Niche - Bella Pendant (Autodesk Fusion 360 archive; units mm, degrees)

design "Bella" references "Niche - Chief Architect - Luxe Single Pendant Cordset", "Bella", "Luxe Single Pendant Cordset - 4ft Standard"
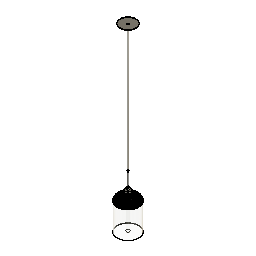
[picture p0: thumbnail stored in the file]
external_derived "ExternalDerived1" bodies "Bella"
external_derived "ExternalDerived2" bodies "Socket Body", "Shade Ring", "Shade Ring +Collar", "Socket", "Body1", "Metal Strain Relief", "Fabric Cord (1)", "Stem (Threaded)"
move "Move1"
external_derived "ExternalDerived3" bodies "T8-Bulb"
move "Move2" TranslateX 0 TranslateY 0 TranslateZ 25.4
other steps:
derived_base_feature "Derived Base Feature1" bodies "Body8", "Bella"
derived_base_feature "Derived Base Feature2" bodies "Socket Body", "Shade Ring", "Shade Ring +Collar", "Socket", "Body1", "Metal Strain Relief", "Fabric Cord (1)", "Stem (Threaded)"
derived_base_feature "Derived Base Feature3" bodies "T8-Bulb"
named bodies: "Body8", "Bella", "Socket Body", "Shade Ring", "Shade Ring +Collar", "Socket", "Body1", "Metal Strain Relief", "Fabric Cord (1)", "Stem (Threaded)", "Cap (Threaded)", "T8-Bulb"

design "Luxe Single Pendant Cordset - 4ft Standard" references "Luxe Canopy - Single Pendant Cordset"
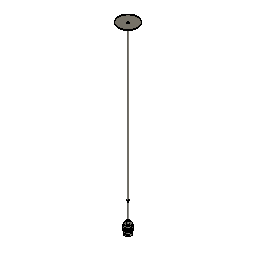
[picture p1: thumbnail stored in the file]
external_derived "ExternalDerived2" bodies "Cap (Threaded)"
move "Move1"
move "Move2"
offset_faces "OffsetFaces1" distance 1051.56
move "Move3"
move "Move4"
move "Move5"
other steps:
derived_base_feature "Derived Base Feature9" bodies "Socket Body", "Shade Ring", "Shade Ring +Collar", "Socket"
derived_base_feature "Derived Base Feature10" bodies "Body1"
derived_base_feature "Derived Base Feature12" bodies "Metal Strain Relief"
derived_base_feature "Derived Base Feature13" bodies "Fabric Cord (1)"
derived_base_feature "Derived Base Feature14" bodies "Stem (Threaded)"
derived_base_feature "Derived Base Feature15" bodies "Cap 9Threaded)", "Cap (Threaded)"
named bodies: "Socket Body", "Shade Ring", "Shade Ring +Collar", "Socket", "Metal Strain Relief", "Fabric Cord (1)", "Stem (Threaded)", "Cap 9Threaded)", "Body1", "Cap (Threaded)", "5M Set Screw"

design "Luxe Canopy - Single Pendant Cordset" references "M5 Set Screw", "Canopy Mounting Bar Screw", "Canopy Mounting Bar", "Plastic Strain Relief", "Luxe Cordset"
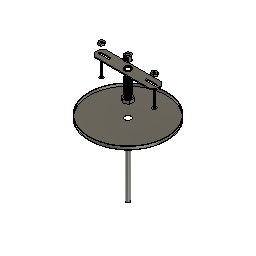
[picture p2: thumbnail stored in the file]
sketch "Sketch1" plane through (0, 0, 0) normal (0, 0, 1) x axis (1, 0, 0)
  circle C1 centre (0, 0) radius 63.5
  point P1 (0, 0)
  point P2 (0, 0)
  coincident P1 P2
  dimension "d1" diameter C1 = 127
extrude "Extrude1" new body sketch "Sketch1" along normal blind 5.08
shell "Shell1" innerThickness 0.762
hole "Hole1" HoleDepth 35.56 HoleDiameter 10.16 TipAngle 118
component_from_bodies "Body->Comp1"
component_insert "Component Insert1"
component_insert "Component Insert2"
component_insert "Component Insert3"
sketch "Sketch2" plane through (0, 0, 0) normal (0, 0, 1) x axis (1, 0, 0)
  circle C1 centre (0, 0) radius 3.175
  point P1 (0, 0)
  point P2 (0, 0)
  coincident P1 P2
  dimension "d8" diameter C1 = 6.35
extrude "Extrude2" new body sketch "Sketch2" along normal blind 127 and against normal blind 127 bodies "Fabric Cord"
component_insert "Component Insert4"
component_insert "Component Insert5"
position "Position1"
sketch "Sketch3" plane through (0, 0, 0.762) normal (0, 0, 1) x axis (-1, 0, 0)
  circle C1 centre (-0.0475, 0.2257) radius 5.08
  circle C2 centre (0, 0) radius 62.738
  circle C3 centre (0, 0) radius 4.826
  concentric C2 C3
  dimension "d13" diameter C3 = 9.652
extrude "Extrude3" new body sketch "Sketch3" profile of C3 along normal blind 25.4 bodies "Threaded Nipple"
shell "Shell2" innerThickness 1.27
thread "Thread1"
sketch "Sketch5" plane through (0, 0, 127) normal (0, 0, 1) x axis (-1, 0, 0)
  line L1 (-6.8191, 3.937) -> (0, 7.874)
  line L2 (-6.8191, -3.937) -> (-6.8191, 3.937)
  line L3 (0, -7.874) -> (-6.8191, -3.937)
  line L4 (6.8191, -3.937) -> (0, -7.874)
  line L5 (6.8191, 3.937) -> (6.8191, -3.937)
  line L6 (0, 7.874) -> (6.8191, 3.937)
  circle C1 centre (0, 0) radius 3.175
  point P2 (0, 0)
  point P9 (0, 0)
  point P3 (0, 7.874)
  coincident P2 P9
  dimension "d20" distance P3 P9 = 7.874
extrude "Extrude4" new body sketch "Sketch5" along normal blind 5.08 bodies "Hex Nut"
move "Move1"
thread "Thread2"
move "Move2" TranslateX 0 TranslateY 0 TranslateZ -55.88
move "Move3" TranslateX 0 TranslateY 0 TranslateZ 60.96
position "Position2"
sketch "Sketch6" plane through (0, 0, 0) normal (0, 0, 1) x axis (1, 0, 0)
  circle C1 centre (0, 0) radius 9.525
  point P1 (0, 0)
  point P2 (0, 0)
  coincident P1 P2
  dimension "d29" diameter C1 = 19.05
extrude "Extrude5" new body sketch "Sketch6" along normal blind 16.129 bodies "Metal Strain Relief"
move "Move4" TranslateX 0 TranslateY 0 TranslateZ -86.36
hole "Hole2" HoleDepth 10.16 HoleDiameter 5.08 TipAngle 118
hole "Hole3" HoleDepth 4.064 HoleDiameter 7.62 TipAngle 180
hole "Hole4" HoleDepth 12.192 HoleDiameter 9.144 TipAngle 180
thread "Thread3" ThreadOffset 0 ThreadLength 6.096
move "Move1" TranslateX 0 TranslateY 0 TranslateZ 68.58
move "Move5" TranslateX 0 TranslateY 0 TranslateZ 138.43
component_insert "Component Insert6"
external_derived "ExternalDerived1" bodies "5M Set Screw"
move "Move6" TranslateX 0 TranslateY 0 TranslateZ -185.42
copy_paste_bodies "CopyPasteBodies1"
move "Move7" TranslateX 0 TranslateY 0 TranslateZ -12.7
offset_faces "OffsetFaces1" distance -152.4
move "Move8"
component_from_bodies "Body->Comp2"
component_from_bodies "Body->Comp3"
component_from_bodies "Body->Comp4"
component_from_bodies "Body->Comp5"
hole "Hole1" HoleDepth 25.4 HoleDiameter 6.35 TipAngle 180
sketch "Sketch7" plane through (0, 0, 0) normal (0, 0, 1) x axis (1, 0, 0)
  line L1 (49.784, 3.9595) -> (52.07, 0)
  line L2 (45.212, 3.9595) -> (49.784, 3.9595)
  line L3 (42.926, 0) -> (45.212, 3.9595)
  line L4 (45.212, -3.9595) -> (42.926, 0)
  line L5 (49.784, -3.9595) -> (45.212, -3.9595)
  line L6 (52.07, 0) -> (49.784, -3.9595)
  point P2 (52.07, 0)
  point P8 (47.498, 0)
  dimension "d63" distance P2 P8 = 4.572
extrude "Extrude6" new body sketch "Sketch7" along normal blind 3.175 bodies "Mounting Hex Nut"
hole "Hole5" HoleDepth 25.4 HoleDiameter 3.81 TipAngle 180
thread "Thread4"
move "Move9"
component_from_bodies "Body->Comp6"
copy_paste "CopyPaste1"
move "Move10"
derived_base_feature "Derived Base Feature3" bodies "Stem (Threaded)", "Cap 9Threaded)"
move "Move11"
component_from_bodies "Body->Comp7"
component_from_bodies "Body->Comp8"
component_from_bodies "Body->Comp9"
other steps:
base_feature "Base Feature1"
base_feature "Base Feature1" bodies "Stem (Threaded)"
base_feature "Base Feature1" bodies "Cap 9Threaded)"
base_feature "Base Feature1" bodies "Fabric Cord"
base_feature "Base Feature1" bodies "Metal Strain Relief"
base_feature "Base Feature1" bodies "Mounting Hex Nut"
base_feature "Base Feature1" bodies "Hex Nut"
base_feature "Base Feature1" bodies "Fabric Cord (1)"
base_feature "Base Feature1" bodies "Threaded Nipple"
derived_base_feature "Derived Base Feature1" bodies "Socket Body", "Shade Ring", "Shade Ring +Collar", "Socket", "Rigid Stem"
derived_base_feature "Derived Base Feature2" bodies "5M Set Screw"
base_feature "Base Feature1" bodies "Fabric Cord", "Fabric Cord (1)"
create_component "CreateComponent1"
remove_body "RemoveBody1"
create_component "CreateComponent2"
remove_body "RemoveBody2"
create_component "CreateComponent3"
remove_body "RemoveBody3"
create_component "CreateComponent4"
remove_body "RemoveBody4"
create_component "CreateComponent5"
remove_body "RemoveBody5"
create_component "CreateComponent6"
remove_body "RemoveBody6"
create_component "CreateComponent7"
remove_body "RemoveBody7"
create_component "CreateComponent8"
remove_body "RemoveBody8"
create_component "CreateComponent9"
remove_body "RemoveBody9"
named bodies: "Fabric Cord", "Threaded Nipple", "Hex Nut", "Metal Strain Relief", "Socket Body", "Shade Ring", "Shade Ring +Collar", "Socket", "Rigid Stem", "5M Set Screw", "Fabric Cord (1)", "Mounting Hex Nut", "Stem (Threaded)", "Cap 9Threaded)"

design "Bella" references "Niche_Bella_Single_Pendant"
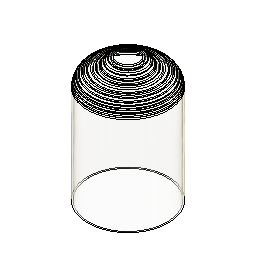
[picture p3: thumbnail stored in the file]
external_derived "ExternalDerived" bodies "Bella"
fillet "Fillet1" radius 22.86
fillet "Fillet2" radius 22.86
fillet "Fillet3" radius 22.86
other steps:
derived_base_feature "Derived Base Feature" bodies "Bella"
named bodies: "Bella"

design "M5 Set Screw"
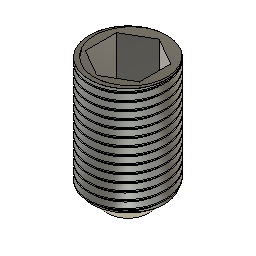
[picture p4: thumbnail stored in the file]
sketch "Sketch1" plane through (0, 0, 0) normal (0, 0, 1) x axis (1, 0, 0)
  circle C1 centre (0, 0) radius 2.5
  point P1 (0, 0)
  point P2 (0, 0)
  coincident P1 P2
  dimension "d1" diameter C1 = 5
extrude "Extrude1" new body sketch "Sketch1" along normal blind 8
sketch "Sketch2" plane through (0, 0, 8) normal (0, 0, 1) x axis (-1, 0, 0)
  line L1 (-1.7321, 1) -> (0, 2)
  line L2 (-1.7321, -1) -> (-1.7321, 1)
  line L3 (0, -2) -> (-1.7321, -1)
  line L4 (1.7321, -1) -> (0, -2)
  line L5 (1.7321, 1) -> (1.7321, -1)
  line L6 (0, 2) -> (1.7321, 1)
  circle C1 centre (0, 0) radius 2.5
  point P2 (0, 0)
  point P9 (0, 0)
  coincident P2 P9
extrude "Extrude2" cut sketch "Sketch2" profile of L1 L2 L3 L4 L5 L6 against normal blind 3
thread "Thread1" ThreadOffset 0.99 ThreadLength 7
chamfer "Chamfer1" distance 1.15

design "Luxe Cordset" references "M5 Set Screw"
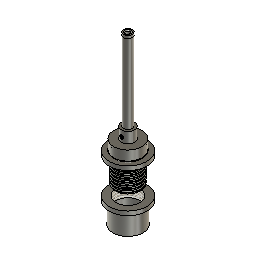
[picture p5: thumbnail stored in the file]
sketch "Sketch1" plane through (0, 0, 0) normal (0, 0, 1) x axis (1, 0, 0)
  circle C1 centre (0, 0) radius 20.6
  point P1 (0, 0)
  point P2 (0, 0)
  coincident P1 P2
  dimension "d11" diameter C1 = 41.2
extrude "Extrude1" new body sketch "Sketch1" along normal blind 14 bodies "Socket Body"
sketch "Sketch2" plane through (0, 0, 14) normal (0, 0, 1) x axis (-1, 0, 0)
  circle C1 centre (0, 0) radius 20.6
  circle C2 centre (0, 0) radius 9.6
  concentric C1 C2
  dimension "d3" diameter C2 = 19.2
extrude "Extrude2" add sketch "Sketch2" profile of C2 along normal blind 15.75
sketch "Sketch3" plane through (0, 0, 29.75) normal (0, 0, 1) x axis (-1, 0, 0)
  circle C1 centre (0, 0) radius 9.6
  circle C2 centre (0, 0) radius 5.75
  concentric C1 C2
  dimension "d6" diameter C2 = 11.5
extrude "Extrude3" new body sketch "Sketch3" profile of C2 along normal blind 114 bodies "Rigid Stem"
move "Move1"
sketch "Sketch4" plane through (0, 0, 203.75) normal (0, 0, 1) x axis (-1, 0, 0)
  circle C1 centre (0, 0) radius 5.75
  circle C2 centre (0, 0) radius 27.5
  dimension "d10" diameter C2 = 55
extrude "Extrude4" new body sketch "Sketch4" profile of C2 along normal blind 6 bodies "Shade Ring"
hole "Hole1" HoleDepth 25 HoleDiameter 42.75 TipAngle 118
sketch "Sketch5" plane through (0, 0, 0) normal (0, 0, 1) x axis (1, 0, 0)
  circle C1 centre (0, 0) radius 22
  point P1 (0, 0)
  point P2 (0, 0)
  coincident P1 P2
  dimension "d18" diameter C1 = 44
move "Move2"
copy_paste_bodies "CopyPasteBodies1"
move "Move3"
sketch "Sketch6" plane through (0, 0, 60) normal (0, 0, -1) x axis (1, 0, 0)
  circle C1 centre (0, 0) radius 20.6
  circle C2 centre (0, 0) radius 21.375
  circle C3 centre (0, 0) radius 20
  concentric C1 C2
  concentric C1 C3
  dimension "d21" diameter C2 = 42.75
  dimension "d24" diameter C3 = 40
cylinder_primitive "CylinderPrimitive1" Height 8 Diameter 42.75
thread "Thread1"
thread "Thread3"
hole "Hole2" HoleDepth 18 HoleDiameter 39 TipAngle 180
move "Move4"
move "Move5"
move "Move6"
hole "Hole3" HoleDepth 114 HoleDiameter 7.6 TipAngle 180
derived_base_feature "Derived Base Feature" bodies "Socket"
move "Move7"
scale "Scale1" ScaleX 1.2 ScaleY 1.2
move "Move8"
sketch "Sketch8" plane through (0, 0, -23.9827) normal (0, 0, -1) x axis (1, 0, 0)
  circle C1 centre (0, -0.036) radius 27.5
  circle C2 centre (0, -0.036) radius 22
  circle C3 centre (0, -0.036) radius 19.5
  dimension "d36" diameter C2 = 44
  dimension "d42" = -2.5
extrude "Extrude7" add sketch "Sketch8" profile of C2 C3 along normal blind 30
offset_faces "OffsetFaces1" distance 2.75
offset_faces "OffsetFaces2" distance -9
thread "Thread2"
move "Move9"
move "Move10"
move "Move11"
scale "Scale2" ScaleZ 1.2
move "Move12"
move "Move13"
move "Move14"
move "Move15"
move "Move16"
split_face "SplitFace1"
move "Move17"
move "Move18"
move "Move19"
move "Move20"
move "Move21"
move "Move22"
move "Move23"
move "Move24"
move "Move25"
move "Move26"
move "Move27"
thread "Thread4"
move "Move28"
move "Move29"
move "Move30"
hole "Hole4" HoleDepth 21 HoleDiameter 39.35 TipAngle 180
hole "Hole5" HoleDepth 9 HoleDiameter 5 TipAngle 180
move "Move31"
move "Move32"
hole "Hole6" HoleDepth 20 HoleDiameter 10 TipAngle 180
move_face "MoveFace3"
move "Move33"
move "Move34"
move "Move35"
move "Move36"
move "Move37"
thread "Thread5" ThreadOffset 0 ThreadLength 6
thread "Thread6" ThreadOffset 0 ThreadLength 6
move "Move38"
move "Move39"
move "Move40"
move "Move41"
component_insert "Component Insert"
thread "Thread7" ThreadOffset 0.5 ThreadLength 5.337
chamfer "Chamfer1" distance 0.5 distance 0.35
sketch "Sketch12" plane through (0, 0, 0) normal (0, 0, 1) x axis (1, 0, 0)
  circle C1 centre (0, 0) radius 6.35
  dimension "d60" diameter C1 = 12.7
extrude "Extrude8" new body sketch "Sketch12" along normal blind 115 bodies "Stem (Threaded)"
hole "Hole7" HoleDepth 115 HoleDiameter 9.65 TipAngle 118
thread "Thread8" ThreadOffset 0 ThreadLength 12.5
thread "Thread9" ThreadOffset 0 ThreadLength 12.5
sketch "Sketch13" plane through (0, 0, 0) normal (0, 0, 1) x axis (1, 0, 0)
  circle C1 centre (0, 0) radius 6.35
  point P1 (0, 0)
  point P2 (0, 0)
  coincident P1 P2
  dimension "d70" diameter C1 = 12.7
extrude "Extrude9" new body sketch "Sketch13" along normal blind 4 bodies "Cap 9Threaded)"
sketch "Sketch14" plane through (0, 0, 4) normal (0, 0, 1) x axis (-1, 0, 0)
  circle C1 centre (0, 0) radius 6.35
  circle C2 centre (0, 0) radius 4.5
  concentric C1 C2
  dimension "d73" diameter C2 = 9
extrude "Extrude10" add sketch "Sketch14" profile of C2 against normal blind 14
thread "Thread10"
hole "Hole8" HoleDepth 115 HoleDiameter 6.5 TipAngle 118 CSDiameter 9 CSAngle 90
move "Move42"
move "Move43"
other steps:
base_feature "Base Feature" bodies "Shade Ring +Collar"
named bodies: "Socket Body", "Shade Ring", "Shade Ring +Collar", "Socket", "Rigid Stem", "Stem (Threaded)", "Cap 9Threaded)"

design "Niche - Chief Architect - Luxe Single Pendant Cordset"
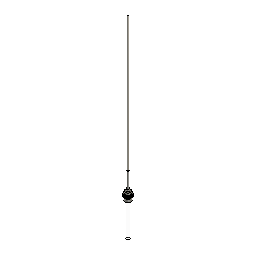
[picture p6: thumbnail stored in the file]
derived_base_feature "Derived Base Feature" bodies "Socket Body", "Shade Ring", "Shade Ring +Collar", "Socket", "Canopy", "Metal Strain Relief", "Fabric Cord (1)", "Stem (Threaded)"
remove_body "RemoveBody1"
remove_body "RemoveBody2"
split "Split1" bodies "Socket Body (1)"
remove_body "RemoveBody3"
align "Align1"
hole "Hole1" HoleDepth 19.05 HoleDiameter 8.89 TipAngle 118
combine "Combine1" bodies "Shade Ring"
split "Split2" bodies "Socket (1)"
remove_body "RemoveBody4"
split "Split3" bodies "Fabric Cord (1) (1)"
remove_body "RemoveBody5"
combine "Combine2" bodies "Socket Body"
align "Align2"
combine "Combine3" bodies "Metal Strain Relief"
sketch "Sketch1" plane through (0, 0, 0) normal (0, 1, 0) x axis (1, 0, 0)
  line L1 (13.1098, 24.9049) -> (-12.2902, 24.9049)
  line L2 (18.1898, 37.1766) -> (18.1898, 29.9849)
  line L3 (-17.3702, 29.9849) -> (-17.3702, 36.7132)
  line L4 (0, 132.969) -> (0, 24.9049)
  arc A1 centre (0, 86.36) radius 46.609 clockwise from (-22.6031, 45.5985) to (23.276, 45.979)
  arc A2 centre (-27.5302, 36.7132) radius 10.16 clockwise from (-22.6031, 45.5985) to (-17.3702, 36.7132)
  arc A3 centre (28.3498, 37.1766) radius 10.16 clockwise from (18.1898, 37.1766) to (23.276, 45.979)
  arc A4 centre (-12.2902, 29.9849) radius 5.08 clockwise from (-12.2902, 24.9049) to (-17.3702, 29.9849)
  arc A5 centre (13.1098, 29.9849) radius 5.08 clockwise from (18.1898, 29.9849) to (13.1098, 24.9049)
  point P5 (18.1898, 43.4469)
  point P3 (-17.3702, 24.9049)
  point P4 (18.1898, 24.9049)
  point P18 (0, 24.9049)
  point P19 (0, 132.969)
  horizontal L1
  vertical L2
  vertical L3
  tangent A1 A2
  tangent L3 A2
  coincident P5 L2
  coincident P5 A1
  tangent L2 A3
  tangent A1 A3
  equal A2 A3
  coincident P3 L1
  coincident P3 L3
  tangent L1 A4
  tangent L3 A4
  coincident P4 L1
  coincident P4 L2
  tangent L1 A5
  tangent L2 A5
  coincident L1 P18
  coincident A1 P19
  perpendicular L1 L4
  dimension "d4" diameter A1 = 93.218
  dimension "d5" distance P3 P4 = 35.56
  dimension "d6" distance P4 P5 = 18.542
  dimension "d7" radius A2 = 10.16
  dimension "d8" radius A4 = 5.08
  dimension "d9" radius A5 = 5.08
revolve "Revolve1" sketch "Sketch1" AlongAngle 360 bodies "G30-Bulb"
move "Move1"
sketch "Sketch2" plane through (0, 0, 0) normal (0, 1, 0) x axis (1, 0, 0)
  line L1 (12.7, 0) -> (-12.7, 0)
  line L2 (12.7, 152.4) -> (12.7, 0)
  line L3 (-12.7, 0) -> (-12.7, 152.4)
  line L4 (0, 165.1) -> (0, 0)
  arc A1 centre (0, 152.4) radius 12.7 clockwise from (-12.7, 152.4) to (12.7, 152.4)
  point P1 (0, 0)
  point P7 (0, 0)
  point P8 (0, 165.1)
  horizontal L1
  vertical L2
  vertical L3
  coincident P1 P7
  midpoint A1 P8
  perpendicular L1 L4
revolve "Revolve2" sketch "Sketch2" AlongAngle 360 bodies "T9-Bulb"
move "Move2"
sketch "Sketch3" plane through (0, 0, 0) normal (0, 1, 0) x axis (1, 0, 0)
  line L1 (12.7, 0) -> (-12.7, 0)
  line L2 (12.7, 254) -> (12.7, 0)
  line L3 (-12.7, 0) -> (-12.7, 254)
  line L4 (0, 266.7) -> (0, 0)
  arc A1 centre (0, 254) radius 12.7 clockwise from (-12.7, 254) to (12.7, 254)
  point P1 (0, 0)
  point P7 (0, 0)
  point P8 (0, 266.7)
  horizontal L1
  vertical L2
  vertical L3
  coincident P1 P7
  midpoint A1 P8
  perpendicular L1 L4
revolve "Revolve3" sketch "Sketch3" AlongAngle 360 bodies "T8-Bulb"
move "Move3"
move "Move4"
move "Move5"
sketch "Sketch4" plane through (0, 0, 0) normal (0, 1, 0) x axis (1, 0, 0)
  line L1 (15.875, -8.763) -> (-15.875, -8.763)
  line L2 (15.875, 22.987) -> (15.875, -8.763)
  line L3 (-15.875, 22.987) -> (15.875, 22.987)
  line L4 (-15.875, -8.763) -> (-15.875, 22.987)
  line L5 (0, 22.987) -> (0, -8.763)
  point P6 (0, -8.763)
  point P7 (0, 22.987)
  point P2 (-15.875, -8.763)
  point P3 (15.875, -8.763)
  point P5 (-15.875, 22.987)
  horizontal L1
  vertical L2
  horizontal L3
  vertical L4
  midpoint L1 P6
  midpoint L3 P7
  dimension "d13" distance P2 P3 = 31.75
  dimension "d14" distance P2 P5 = 31.75
revolve "Revolve4" sketch "Sketch4" AlongAngle 360 bodies "Bulb Extender"
move "Move6"
sketch "Sketch5" plane through (0, 0, 0) normal (0, 1, 0) x axis (1, 0, 0)
  line L1 (-12.7, 35.56) -> (12.7, 35.56)
  line L2 (-12.7, 5.08) -> (-12.7, 35.56)
  line L3 (12.7, 5.08) -> (-12.7, 5.08)
  line L4 (12.7, 35.56) -> (12.7, 5.08)
  line L5 (-12.7, 5.08) -> (12.7, 35.56)
  line L6 (12.7, 5.08) -> (-12.7, 35.56)
  line L7 (0, 35.56) -> (0, 5.08)
  point P6 (0, 20.32)
  point P7 (0, 5.08)
  point P8 (0, 35.56)
  horizontal L1
  perpendicular L1 L2
  parallel L1 L3
  parallel L2 L4
  coincident L5 P6
  coincident L6 P6
  midpoint L3 P7
  midpoint L1 P8
revolve "Revolve5" sketch "Sketch5" AlongAngle 360 bodies "Y-Spliter"
sketch "Sketch6" plane through (0, 0, 0) normal (0, 1, 0) x axis (1, 0, 0)
  line L1 (-55.88, 64.9514) -> (-21.59, 64.9514)
  line L2 (-55.88, 35.7414) -> (-55.88, 64.9514)
  line L3 (-21.59, 35.7414) -> (-55.88, 35.7414)
  line L4 (-21.59, 64.9514) -> (-21.59, 35.7414)
  line L5 (-55.88, 35.7414) -> (-21.59, 64.9514)
  line L6 (-21.59, 35.7414) -> (-55.88, 64.9514)
  line L7 (-38.735, 64.9514) -> (-38.735, 35.7414)
  point P6 (-38.735, 50.3464)
  point P7 (-38.735, 35.7414)
  point P8 (-38.735, 64.9514)
  point P4 (-55.88, 35.7414)
  point P5 (-21.59, 35.7414)
  point P2 (-21.59, 64.9514)
  horizontal L1
  perpendicular L1 L2
  parallel L1 L3
  parallel L2 L4
  coincident L5 P6
  coincident L6 P6
  midpoint L3 P7
  midpoint L1 P8
  dimension "d17" distance P4 P5 = 34.29
  dimension "d18" distance P2 P5 = 29.21
revolve "Revolve6" sketch "Sketch6" AlongAngle 360
chamfer "Chamfer1" distance 7.62
move "Move7"
mirror "Mirror1" mirrorStitchTolerance 0.1016
move "Move8"
combine "Combine4"
move "Move9"
sketch "Sketch7" plane through (0, 0, 0) normal (0, 1, 0) x axis (1, 0, 0)
  line L1 (-15.24, 40.64) -> (-15.24, 48.1816)
  line L2 (12.7, 38.1) -> (-12.7, 38.1)
  line L3 (15.24, 48.1816) -> (15.24, 40.64)
  line L4 (0, 100.1623) -> (0, 38.1)
  arc A1 centre (0, 76.2) radius 23.9623 clockwise from (-19.7282, 62.5988) to (19.7282, 62.5988)
  arc A2 centre (-40.64, 48.1816) radius 25.4 clockwise from (-19.7282, 62.5988) to (-15.24, 48.1816)
  arc A3 centre (40.64, 48.1816) radius 25.4 clockwise from (15.24, 48.1816) to (19.7282, 62.5988)
  arc A4 centre (-12.7, 40.64) radius 2.54 clockwise from (-12.7, 38.1) to (-15.24, 40.64)
  arc A5 centre (12.7, 40.64) radius 2.54 clockwise from (15.24, 40.64) to (12.7, 38.1)
  point P15 (0, 38.1)
  point P16 (0, 100.1623)
  parallel L1 L3
  tangent A1 A2
  tangent L1 A2
  tangent A1 A3
  tangent L3 A3
  tangent L1 A4
  tangent L2 A4
  tangent L2 A5
  tangent L3 A5
  midpoint L2 P15
  midpoint A1 P16
  perpendicular L2 L4
  dimension "d23" radius A2 = 25.4
  dimension "d24" radius A3 = 25.4
  dimension "d25" radius A4 = 2.54
  dimension "d26" radius A5 = 2.54
revolve "Revolve7" sketch "Sketch7" AlongAngle 360 bodies "A15-Bulb"
move "Move10"
copy_paste_bodies "CopyPasteBodies1"
copy_paste_bodies "CopyPasteBodies2"
move "Move11"
mirror "Mirror2" mirrorStitchTolerance 0.1016 bodies "A15-Bulb (1) (1)"
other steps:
base_feature "Base Feature1" bodies "Y-Spliter", "Bulb Extender", "Y-Spliter (1)", "Bulb Extender (1)"
base_feature "Base Feature2" bodies "A15-Bulb", "A15-Bulb (1)"
named bodies: "Socket Body", "Shade Ring", "Shade Ring +Collar", "Socket", "Canopy", "Metal Strain Relief", "Fabric Cord (1)", "Stem (Threaded)", "Adapter", "5M Set Screw", "Body1 (1)", "Socket Body (1)", "Socket (1)", "Fabric Cord (1) (1)", "G30-Bulb", "T9-Bulb", "T8-Bulb", "Bulb Extender", "Y-Spliter", "A15-Bulb", "Y-Spliter (1)", "Bulb Extender (1)", "A15-Bulb (1)", "A15-Bulb (1) (1)"

design "Plastic Strain Relief"
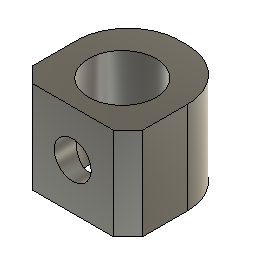
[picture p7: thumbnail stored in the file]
base_feature "Base Feature" bodies "strainrelief"
named bodies: "strainrelief"

design "Canopy Mounting Bar Screw"
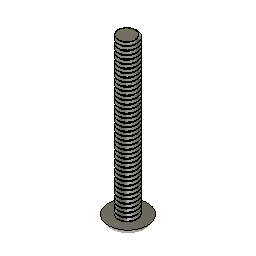
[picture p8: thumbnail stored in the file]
base_feature "Base Feature" bodies "screw1"
named bodies: "screw1"

design "Niche_Bella_Single_Pendant"
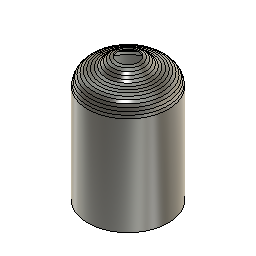
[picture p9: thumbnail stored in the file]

design "Canopy Mounting Bar"
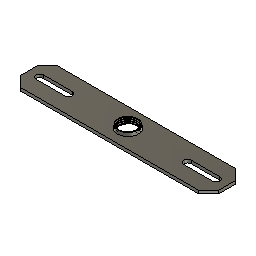
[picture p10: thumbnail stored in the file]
base_feature "Base Feature" bodies "mountingbar"
named bodies: "mountingbar"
